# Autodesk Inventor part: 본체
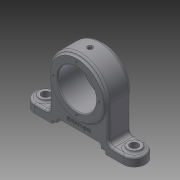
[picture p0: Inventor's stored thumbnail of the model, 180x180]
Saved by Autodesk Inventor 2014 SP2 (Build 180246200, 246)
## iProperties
Created: 2019-05
Part Number: 본체
Material: 일반
Document SubType Name: Modeling
Designer: gs
Density: 1 g/cm^3
Appearance: 기본값
Author: gs
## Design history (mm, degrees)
sketch "스케치1"
  geometry: L1 (-75, 0)-(75, 0); L2 (75, 0)-(75, 12); L3 (-75, 12)-(-75, 0); L4 (-40, 60)-(-40, 12); L5 (40, 60)-(40, 12); L6 (75, 12)-(40, 12); L7 (-40, 12)-(-75, 12); A1 r 40 centre (0, 60) between (40, 60) and (-40, 60); 2 further points
  constraints: 14 end point, 3 parallel, 3 perpendicular, 2 point on circle, 2 tangent, 1 centre point, 1 coincident, 1 horizontal, 1 midpoint, 1 vertical alignment
  dimensions: "d0" = 150 distance between parallel lines of L2 L3; "d2" = 40 radius of A1; "d3" = 60 distance from line of L1 A1.centre; "d4" = 12 distance between parallel lines of L6 L1; "d5" = 0 distance between parallel lines of L6 L7; "d37" = 100 dimension on A1 L1 (derived)
extrude "돌출1" new body sketch "스케치1" stored distance "d6" = 30; taper "d7" = 0 deg; taper "d17" = 0 deg
sketch "스케치3"
  geometry: C1 r 36 at (0, 60); A1 r 40 centre (0, 60) between (40, 60) and (-40, 60) reference; 1 further point
  constraints: 1 centre point, 1 coincident
  dimensions: "d11" = 72 diameter of C1
extrude "돌출3" join sketch "스케치3" distance "d12" = 3; taper "d13" = 0 deg
sketch "스케치4"
  geometry: L1 (-75, 0)-(75, 0) reference; L2 (-30, 0)-(30, 0); L3 (30, 0)-(30, 10); L4 (30, 10)-(-30, 10); L5 (-30, 10)-(-30, 0); 3 further points
  constraints: 8 end point, 2 midpoint, 2 parallel, 1 coincident, 1 collinear, 1 horizontal, 1 perpendicular
  dimensions: "d14" = 60 distance between parallel lines of L3 L5; "d15" = 10 distance between parallel lines of L1 L4
extrude "돌출4" cut sketch "스케치4" stored distance "d16" = 3; taper "d17" = 0 deg
sketch "스케치5"
  geometry: L1 (-75, 0)-(-30, 0) reference; L2 (-36, 0)-(36, 0); L3 (36, 0)-(36, 4); L4 (36, 4)-(-36, 4); L5 (-36, 4)-(-36, 0); 2 further points
  constraints: 8 end point, 2 parallel, 1 coincident, 1 collinear, 1 horizontal, 1 midpoint, 1 perpendicular
  dimensions: "d18" = 72 distance between parallel lines of L3 L5; "d19" = 4 distance between parallel lines of L2 L4
extrude "돌출5" cut sketch "스케치5" stored distance "d21" = 3; taper "d22" = 0 deg
sketch "스케치6"
  geometry: L1 (0, 0)-(35, 0) reference; L2 (0, -30)-(0, 0) reference; C1 r 9 at (15, -15); 1 further point
  constraints: 1 centre point
  dimensions: "d23" = 18 diameter of C1; "d24" = 15 distance from line of L2 C1.centre; "d25" = 15 distance from line of L1 C1.centre
extrude "돌출6" join sketch "스케치6" distance "d26" = 3; taper "d27" = 0 deg
hole "구멍1" diameter "d30" = 11; stored, may be unused: countersink angle "d34" = 90 deg, drill point angle "d36" = 118 deg; dims "d28" = 10, "d29" = 10, "d31" = 6, "d32" = 4, "d33" = 2, "d35" = 8
node "작업 평면1"
sketch "스케치7"
  geometry: C1 r 3.5 at (0, 0); 1 further point
  constraints: 1 centre point, 1 coincident
  dimensions: "d39" = 7 diameter of C1
extrude "돌출7" cut sketch "스케치7" distance "d40" = 1; taper "d41" = 0 deg
hole "구멍2" diameter "d44" = 4.917; stored, may be unused: countersink angle "d48" = 90 deg, drill point angle "d50" = 118 deg; dims "d42" = 10, "d43" = 10, "d45" = 8, "d46" = 4, "d47" = 2, "d49" = 10
hole "구멍3" diameter "d53" = 52; stored, may be unused: countersink angle "d57" = 90 deg, drill point angle "d59" = 118 deg; dims "d51" = 10, "d52" = 10, "d54" = 52, "d55" = 4, "d56" = 2, "d58" = 52
sketch "스케치8" dims "d60" = 62
  geometry: C1 r 26 at (0, 0) reference; C2 r 36 at (0, 0) reference; 3 further points
  constraints: 2 vertical alignment, 1 coincident, 2 other
hole "구멍4" sketch "스케치8" at (0, 31) diameter "d62" = 3.242; stored, may be unused: countersink angle "d66" = 90 deg, drill point angle "d68" = 118 deg; dims "d63" = 6, "d64" = 4, "d65" = 2, "d67" = 8
sketch "스케치10"
  geometry: C1 r 26 at (0, 0) reference; C2 r 36 at (0, 0) reference; C3 r 26 at (0, 0); 2 further points
  constraints: 1 centre point, 1 coincident, 1 vertical alignment
  dimensions: "d72" = 52 diameter of C3; "d73" = 26 distance of C1.centre point (0, 26)
hole "구멍5" sketch "스케치10" at (0, 26) diameter "d74" = 3; stored, may be unused: countersink angle "d78" = 90 deg, drill point angle "d80" = 118 deg; dims "d75" = 6, "d76" = 4, "d77" = 2, "d79" = 8
hole "구멍6" diameter "d83" = 2; stored, may be unused: countersink angle "d87" = 90 deg, drill point angle "d89" = 0 deg; dims "d84" = 6, "d85" = 4, "d86" = 2, "d88" = 20, "d90" = 10, "d91" = 10
node "작업 평면2"
sketch "스케치11"
  geometry: C1 r 1 at (0, 0); 1 further point
  constraints: 1 centre point, 1 coincident
  dimensions: "d93" = 2 diameter of C1
extrude "돌출8" cut sketch "스케치11" stored distance "d94" = 20; taper "d95" = 0 deg
sketch "스케치12"
  geometry: L1 (-30, 10)-(30, 10) reference; L2 (-20, 20)-(20, 20); L3 (20, 20)-(20, 14); L4 (20, 14)-(-20, 14); L5 (-20, 14)-(-20, 20); L6 (-20, 17)-(20, 17); L7 (0, 20)-(0, 14); 1 further point
  constraints: 4 end point, 4 midpoint, 1 vertical alignment, 2 other
  dimensions: "d96" = 40 distance of L6.start L6.end; "d97" = 6 distance of L7.start L7.end; "d98" = 7 distance between parallel lines of L1 L6
feature "엠보싱1" sketch "스케치12" dims "d99" = 0.5, "d100" = 0
chamfer "모따기1" distance "d102" = 1; stored, may be unused: second distance "d103" = 2, angle "d104" = 45 deg
fillet "모깎기3" dims "d106" = 15
fillet "모깎기4" dims "d107" = 15
fillet "모깎기5" dims "d108" = 15
fillet "모깎기6" dims "d109" = 6
fillet "모깎기7" dims "d110" = 3
fillet "모깎기8" dims "d111" = 3
fillet "모깎기9" dims "d112" = 3
fillet "모깎기10" dims "d113" = 3
fillet "모깎기11" dims "d114" = 3
node "솔리드1"
mirror "대칭1"
mirror "대칭2"
mirror "대칭3"
pattern_circular "원형 패턴1" dims angle "d70" = 360 deg
mirror "대칭4"
other parameters: "d1" = 12, "d92" = 86
